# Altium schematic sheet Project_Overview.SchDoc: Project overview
size A4; Date: Not used; ApprovedBy: Not used; CheckedBy: Not used; Author: Ph.A; CompanyName: STMicroelectronics; DrawnBy: Not used; Engineer: Not used; Organization: Not used; Address1: Not used; Address2: Not used; Address3: Not used; Address4: Not used; DocumentNumber: Not used; Revision: Not used; SheetNumber: 1; SheetTotal: 8
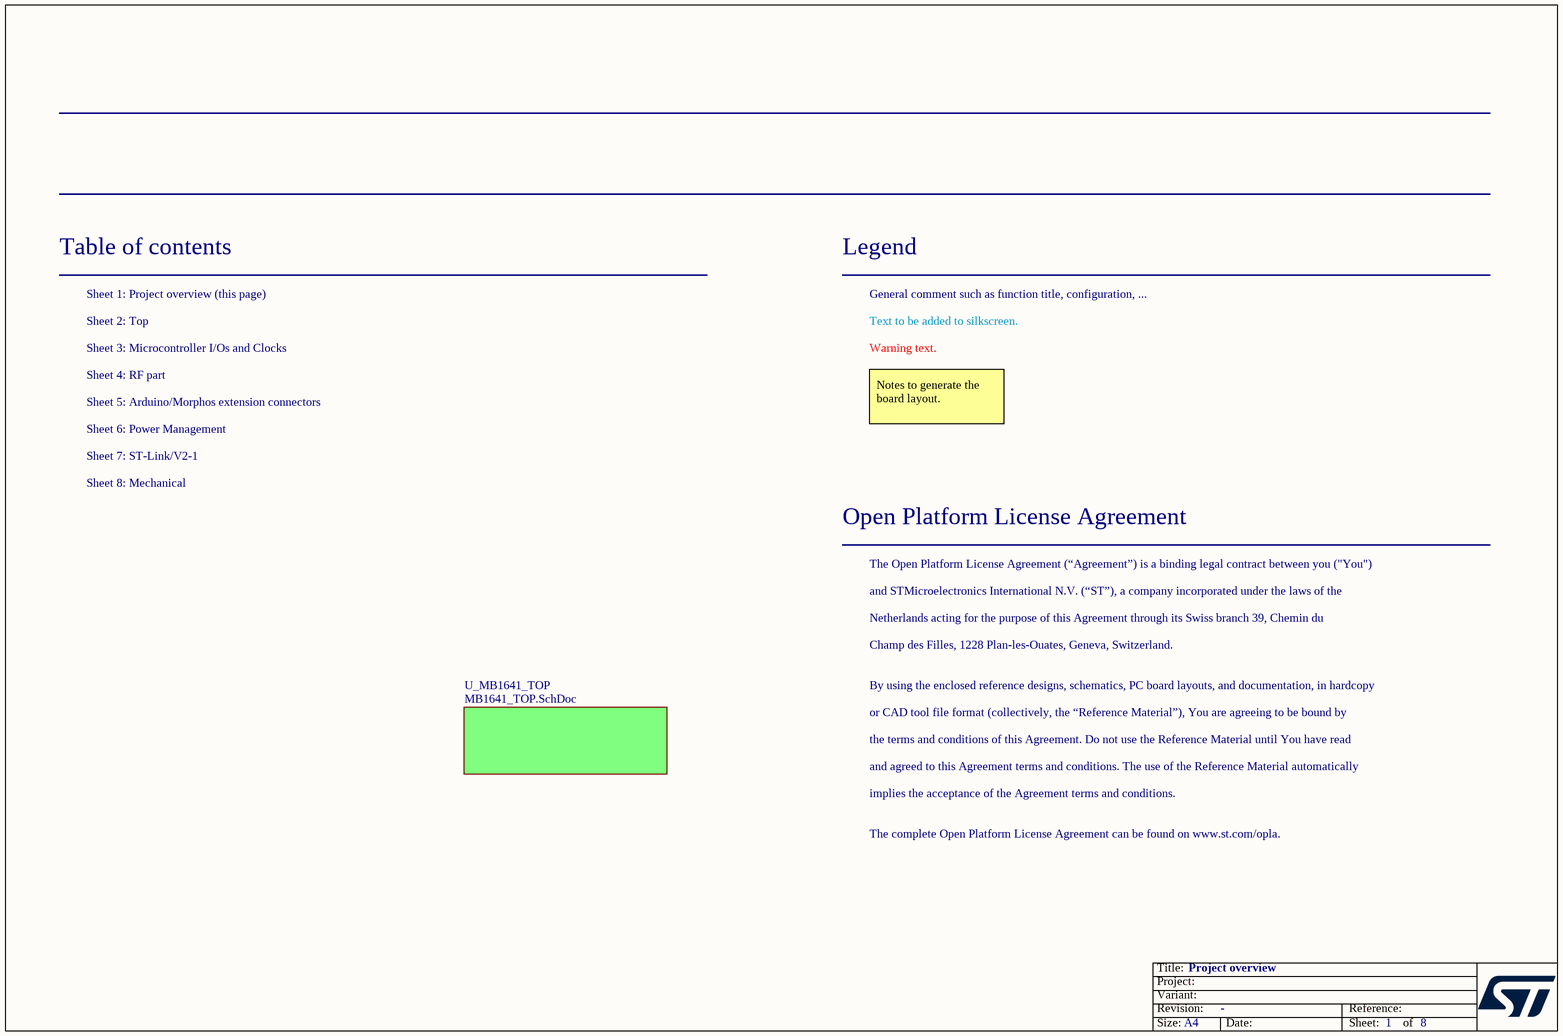
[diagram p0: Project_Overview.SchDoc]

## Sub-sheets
U_MB1641_TOP = MB1641_TOP.SchDoc: no entries

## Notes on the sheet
- Table of contents
- Sheet 1: Project overview (this page)
- Legend
- General comment such as function title, configuration, ...
- Sheet 3: Microcontroller I/Os and Clocks
- Sheet 4: RF part
- Sheet 2: Top
- Text to be added to silkscreen.
- Warning text.
- Sheet 5: Arduino/Morphos extension connectors
- Sheet 6: Power Management
- Notes to generate the board layout.
- Sheet 7: ST-Link/V2-1
- Sheet 8: Mechanical
- Open Platform License Agreement
- The Open Platform License Agreement (“Agreement”) is a binding legal contract between you ("You")
- and STMicroelectronics International N.V. (“ST”), a company incorporated under the laws of the
- Netherlands acting for the purpose of this Agreement through its Swiss branch 39, Chemin du
- Champ des Filles, 1228 Plan-les-Ouates, Geneva, Switzerland.
- By using the enclosed reference designs, schematics, PC board layouts, and documentation, in hardcopy
- or CAD tool file format (collectively, the “Reference Material”), You are agreeing to be bound by
- the terms and conditions of this Agreement. Do not use the Reference Material until You have read
- and agreed to this Agreement terms and conditions. The use of the Reference Material automatically
- implies the acceptance of the Agreement terms and conditions.
- The complete Open Platform License Agreement can be found on www.st.com/opla.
